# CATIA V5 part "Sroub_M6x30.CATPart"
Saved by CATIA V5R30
Part number: Sroub_M6x30
Nomenclature: E1200/6x30
Description: MEUSBURGER
Publications: "DrillHole", "TapHole", "Base"
Bounding box of the stored display mesh (mm): x -4.991 to 4.991, y -5 to 5, z -6 to 30
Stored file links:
  E:\Bakalarka\Model\Forma_v7\Sroub_M6x30.CATPart
  E:\dev\MoldDesign\intel_a\startup\components\MoldCatalog\CapScrew\Meusburger\CapScrew_E1200\TableE1200.txt
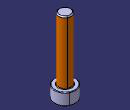
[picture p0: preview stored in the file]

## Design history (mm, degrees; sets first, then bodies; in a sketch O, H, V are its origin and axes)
Parameters
  Ref = "E1200/6x30" {design table}
  L = 30 mm {design table}
  D = 6 mm {design table}
  D1 = 6 mm {design table}
  D3 = 10 mm {design table}
  L1 = 30 mm {design table}
  L2 = 24 mm {design table}
  L3 = 6 mm {design table}
  SW = 5 mm {design table}
  dkren = 4.77 mm {design table}
  L4 = 3 mm {design table}
  R = 0.25 mm {design table}
  R1 = 0.6 mm {design table}
  F = 0.5 mm {design table}
  kdkern = 4.92 mm {design table}
  kd1 = 6.6 mm {design table}
  kl1 = 15 mm {design table}
  kd3 = 11 mm {design table}
  kl3 = 7 mm {design table}
  kl = 42 mm {design table}
  c = 5 mm {design table}
  ThreadString = "M6" {design table}
  Mat = "" {design table}
  HeatTreat = "" {design table}
  SupplierRef = "Meusburger 2017"
  BmpRef = "F_MldCapScrewLD"
  DrillHole_Length = 225 mm
  HeadThick = 6 mm {= L3}
  HeadDiam = 10 mm {= D3}
  ScrewThread = 24 mm {= Thread1.Depth}
  ScrewPitch = 1 mm {= Thread1.Pitch}
Set1 "BaseBody"
  Point1 "Base": (0, 0, 0)
  Plane1: type Offset, RefPlane xy-plane, Offset 225 {= DrillHole_Length}, reversed
Body1 "PartBody" (main body)
  Sketch1 on yz-plane, origin (0, 0, 0), H (0, 0, -1), V (0, 1, 0)
    point P1 (6, 0)
    line L1 (6, 0) -> (6, -5)
    line L2 (6, -5) -> (0, -5)
    line L3 (0, -5) -> (0, -3)
    point P5 (0, -3)
    line L4 (0, -3) -> (-30, -3)
    line L5 (-30, -3) -> (-30, 0)
    point P7 (-30, 0)
    axis line L6 (-30, 0) -> (6, 0)
    point P8 (6, 0)
    construction line L7 (0, -3) -> (0, -3)
    line L8 (0, 0) -> (-30, 0)
    point P9 (-30, -3)
    point P10 (-30, -3)
    line L9 (0, 0) -> (6, 0)
    length L1 = 5 {= D3 /2}
    distance L1 L3 = 6 {= L3}
    distance L4 L6 = 3 {= D /2}
    distance L3 L5 = 30 {= L}
    distance L5 P5 = 30 {= L1}
    coincidence: P1 L6, L6 H, P8 L1, P9 P10, P7 L5, L3 V
    vertical: L1 V, L3 V, L5 V
    horizontal: L2 H, L4 H, L7 H, L8 H, L9 H
  Shaft1: profile Sketch1, axis Sketch1.L6, angle 360
  Sketch2 on face of Shaft1 from Sketch1.L1, origin (0, 0, -6), H (1, 0, 0), V (0, -1, 0)
    point P1 (-1.4434, -2.5)
    point P2 (1.4434, -2.5)
    point P3 (2.8868, 0)
    point P4 (1.4434, 2.5)
    point P5 (-1.4434, 2.5)
    point P6 (-2.8868, 0)
    point P7 (0, -2.5)
    line L1 (-1.4434, -2.5) -> (1.4434, -2.5)
    line L2 (1.4434, -2.5) -> (2.8868, 0)
    line L3 (2.8868, 0) -> (1.4434, 2.5)
    line L4 (1.4434, 2.5) -> (-1.4434, 2.5)
    line L5 (-1.4434, 2.5) -> (-2.8868, 0)
    line L6 (-2.8868, 0) -> (-1.4434, -2.5)
    construction line L7 (0, 0) -> (0, -2.5)
    construction circle A1 centre (0, 0) radius 2.8868
    construction arc A2 centre (-1.4434, 2.5) radius 2.8868 from (1.4434, 2.5) to (-2.8868, 0) cw
    construction arc A3 centre (1.4434, -2.5) radius 2.8868 from (2.8868, 0) to (-1.4434, -2.5) ccw
    point P8 (-1.4434, 2.5)
    point P9 (1.4434, -2.5)
    distance L1 L4 = 5 {= SW}
    coincidence: A1 P1, A1 P2, A1 P3, A1 P4, A1 P5, A1 P6, A2 P4, A2 P6, A2 O, P8 P5, A3 P3, A3 P1, A3 O, P9 P2, P3 H
    midpoint: P7 L1
  Pocket1: profile Sketch2, direction (0, 0, 1), length 3 {= L4}
  Thread1: "M6", diameter 6, depth 24 {= L2}, pitch 1, on face of Shaft1 from Sketch1.L4, from face of Shaft1 from Sketch1.L5
  Fillet1: radius 0.6 {= R1}, on edge [face of Shaft1 from Sketch1.L2 | face of Shaft1 from Sketch1.L1]
  Fillet2: radius 0.25 {= R}, on edge [face of Shaft1 from Sketch1.L3 | face of Shaft1 from Sketch1.L2]
  Fillet3: radius 0.25 {= R}, on edge [face of Shaft1 from Sketch1.L4 | face of Shaft1 from Sketch1.L3]
  Chamfer1: length 0.5 {= F}, angle 45, on edge [face of Shaft1 from Sketch1.L5 | face of Shaft1 from Sketch1.L4]
Body2 "DrillHole"
  Sketch3 on Plane1, origin (22.3066, -22.3066, -225), H (1, 0, 0), V (0, 1, 0)
    point P1 (-22.3066, 22.3066)
    reference projected circle E1 centre (-22.3066, 22.3066) radius 5 from edge [face of Shaft1 from Sketch1.L3 | face of Shaft1 from Sketch1.L2]
    concentricity: E1 P1
  Hole1: placed by Sketch3, at (0, 0, -225) direction (0, 0, 1), diameter 6.6 {= kd1}, depth 255 {= DrillHole_Length +L1}, counterbore diameter 11 {= kd3}, counterbore depth 225 {= DrillHole_Length}
Body3 "TapHole"
  Sketch4 on Plane1, origin (0, 0, -225), H (1, 0, 0), V (0, 1, 0)
    point P1 (0, 0)
    reference projected point E1 (0, 0) from Point1
    coincidence: E1 P1
  Hole2: placed by Sketch4, at (0, 0, -225) direction (0, 0, 1), diameter 4.917, depth 267 {= DrillHole_Length +kl}, V-bottom angle 120, threaded "M6", thread diameter 6, thread depth 267 {= DrillHole_Length +kl}, pitch 1
Relations
  design table "TableE1200", configuration 51, drives Ref, L, D, D1, D3, L1, L2, L3, SW, dkren, L4, R, R1, F, kdkern, kd1, kl1, kd3, kl3, kl, c, ThreadString, Mat, HeatTreat
  Thread1.ThreadDescription = ThreadString
  Hole2.ThreadDescription = ThreadString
